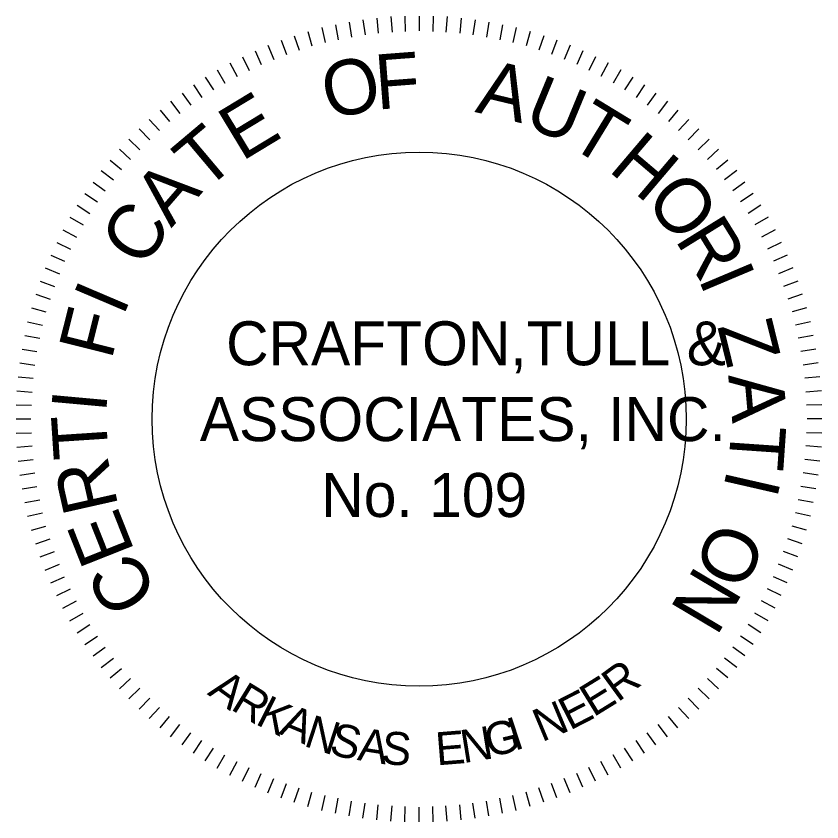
# Model space of a CAD drawing. Extents: x 670147 to 673275, y 705573 to 707613.
# Drawn here: x 672318.1 to 672589.3, y 705642.6 to 705913.8 of the extents above; entities that cross this region are included whole.
import ezdxf

# ---------------------------------------------------------------- set-up
doc = ezdxf.new("R2010")
doc.units = 0
doc.layers.add('R_Border Prem', color=7, linetype='Continuous')

msp = doc.modelspace()

# ---------------------------------------------------------------- linework, layer by layer
at = {"layer": 'R_Border Prem'}
for p, q in [((672444.26, 705913.59), (672444.63, 705908.41)), ((672448.89, 705913.77), (672449.07, 705908.59)), ((672453.7, 705913.77), (672453.7, 705908.78)), ((672458.51, 705913.77), (672458.32, 705908.59)), ((672463.13, 705913.59), (672462.76, 705908.41)), ((672425.58, 705910.81), (672426.5, 705905.82)), ((672430.2, 705911.74), (672430.94, 705906.74)), ((672434.83, 705912.48), (672435.57, 705907.48)), ((672439.45, 705913.03), (672440.01, 705908.04)), ((672467.94, 705913.03), (672467.39, 705908.04)), ((672472.57, 705912.48), (672471.83, 705907.48)), ((672477.19, 705911.74), (672476.45, 705906.74)), ((672481.82, 705910.81), (672480.89, 705905.82)), ((672416.33, 705908.59), (672417.62, 705903.78)), ((672420.95, 705909.89), (672422.06, 705904.89)), ((672486.44, 705909.89), (672485.33, 705904.89)), ((672491.07, 705908.59), (672489.77, 705903.78)), ((672407.26, 705905.63), (672409.11, 705900.82)), ((672411.7, 705907.11), (672413.37, 705902.3)), ((672495.69, 705907.11), (672494.03, 705902.3)), ((672500.13, 705905.63), (672498.28, 705900.82)), ((672402.82, 705903.97), (672404.86, 705899.16)), ((672504.57, 705903.97), (672502.54, 705899.16)), ((672394.31, 705900.08), (672396.53, 705895.46)), ((672398.57, 705902.12), (672400.6, 705897.49)), ((672508.83, 705902.12), (672506.79, 705897.49)), ((672513.08, 705900.08), (672510.86, 705895.46)), ((672390.06, 705898.05), (672392.46, 705893.42)), ((672517.34, 705898.05), (672514.93, 705893.42)), ((672385.8, 705895.64), (672388.39, 705891.2)), ((672521.59, 705895.64), (672519, 705891.2)), ((672381.73, 705893.24), (672384.51, 705888.98)), ((672525.66, 705893.24), (672522.89, 705888.98)), ((672377.85, 705890.65), (672380.62, 705886.39)), ((672529.55, 705890.65), (672526.77, 705886.39)), ((672373.96, 705887.87), (672376.92, 705883.8)), ((672533.43, 705887.87), (672530.47, 705883.8)), ((672370.08, 705885.1), (672373.22, 705881.03)), ((672537.32, 705885.1), (672534.17, 705881.03)), ((672366.56, 705882.14), (672369.71, 705878.25)), ((672540.83, 705882.14), (672537.69, 705878.25)), ((672362.86, 705878.99), (672366.38, 705875.29)), ((672544.53, 705878.99), (672541.02, 705875.29)), ((672359.53, 705875.85), (672363.05, 705872.15)), ((672547.86, 705875.85), (672544.35, 705872.15)), ((672356.02, 705872.33), (672359.72, 705868.82)), ((672551.38, 705872.33), (672547.68, 705868.82)), ((672352.87, 705869), (672356.57, 705865.49)), ((672554.52, 705869), (672550.82, 705865.49)), ((672349.73, 705865.3), (672353.61, 705862.16)), ((672557.67, 705865.3), (672553.78, 705862.16)), ((672346.77, 705861.79), (672350.84, 705858.64)), ((672560.63, 705861.79), (672556.56, 705858.64)), ((672343.99, 705857.9), (672348.06, 705854.94)), ((672563.4, 705857.9), (672559.33, 705854.94)), ((672341.22, 705854.02), (672345.47, 705851.24)), ((672566.18, 705854.02), (672561.92, 705851.24)), ((672338.63, 705850.13), (672342.88, 705847.36)), ((672568.77, 705850.13), (672564.51, 705847.36)), ((672336.22, 705846.06), (672340.66, 705843.47)), ((672571.17, 705846.06), (672566.73, 705843.47)), ((672333.82, 705841.81), (672338.44, 705839.4)), ((672573.58, 705841.81), (672568.95, 705839.4)), ((672331.78, 705837.55), (672336.41, 705835.33)), ((672575.61, 705837.55), (672570.99, 705835.33)), ((672329.75, 705833.3), (672334.37, 705831.26)), ((672577.65, 705833.3), (672573.02, 705831.26)), ((672327.9, 705829.04), (672332.71, 705827.01)), ((672579.5, 705829.04), (672574.69, 705827.01)), ((672326.23, 705824.6), (672331.04, 705822.75)), ((672581.16, 705824.6), (672576.35, 705822.75)), ((672324.75, 705820.16), (672329.56, 705818.5)), ((672582.64, 705820.16), (672577.83, 705818.5)), ((672323.27, 705815.54), (672328.08, 705814.24)), ((672584.12, 705815.54), (672579.31, 705814.24)), ((672321.98, 705810.91), (672326.97, 705809.8)), ((672585.42, 705810.91), (672580.42, 705809.8)), ((672321.05, 705806.29), (672326.05, 705805.36)), ((672586.34, 705806.29), (672581.35, 705805.36)), ((672320.13, 705801.66), (672325.12, 705800.92)), ((672587.27, 705801.66), (672582.27, 705800.92)), ((672319.39, 705797.04), (672324.38, 705796.3)), ((672588.01, 705797.04), (672583.01, 705796.3)), ((672318.83, 705792.41), (672323.83, 705791.86)), ((672588.56, 705792.41), (672583.57, 705791.86)), ((672318.28, 705787.6), (672323.46, 705787.23)), ((672589.12, 705787.6), (672583.94, 705787.23)), ((672318.09, 705782.98), (672323.27, 705782.79)), ((672589.3, 705782.98), (672584.12, 705782.79)), ((672318.09, 705778.17), (672323.09, 705778.17)), ((672589.3, 705778.17), (672584.31, 705778.17)), ((672318.09, 705773.36), (672323.27, 705773.54)), ((672589.3, 705773.36), (672584.12, 705773.54)), ((672318.28, 705768.73), (672323.46, 705769.1)), ((672589.12, 705768.73), (672583.94, 705769.1)), ((672318.83, 705763.92), (672323.83, 705764.48)), ((672588.56, 705763.92), (672583.57, 705764.48)), ((672319.39, 705759.3), (672324.38, 705760.04)), ((672588.01, 705759.3), (672583.01, 705760.04)), ((672320.13, 705754.67), (672325.12, 705755.41)), ((672587.27, 705754.67), (672582.27, 705755.41)), ((672321.05, 705750.05), (672326.05, 705750.97)), ((672586.34, 705750.05), (672581.35, 705750.97)), ((672321.98, 705745.42), (672326.97, 705746.53)), ((672585.42, 705745.42), (672580.42, 705746.53)), ((672323.27, 705740.8), (672328.08, 705742.09)), ((672584.12, 705740.8), (672579.31, 705742.09)), ((672324.75, 705736.17), (672329.56, 705737.84)), ((672582.64, 705736.17), (672577.83, 705737.84)), ((672326.23, 705731.73), (672331.04, 705733.58)), ((672581.16, 705731.73), (672576.35, 705733.58)), ((672327.9, 705727.29), (672332.71, 705729.33)), ((672579.5, 705727.29), (672574.69, 705729.33)), ((672329.75, 705723.04), (672334.37, 705725.07)), ((672577.65, 705723.04), (672573.02, 705725.07)), ((672331.78, 705718.78), (672336.41, 705721)), ((672575.61, 705718.78), (672570.99, 705721)), ((672333.82, 705714.53), (672338.44, 705716.93)), ((672573.58, 705714.53), (672568.95, 705716.93)), ((672336.22, 705710.27), (672340.66, 705712.86)), ((672571.17, 705710.27), (672566.73, 705712.86)), ((672338.63, 705706.2), (672342.88, 705708.98)), ((672568.77, 705706.2), (672564.51, 705708.98)), ((672341.22, 705702.32), (672345.47, 705705.09)), ((672566.18, 705702.32), (672561.92, 705705.09)), ((672343.99, 705698.43), (672348.06, 705701.39)), ((672563.4, 705698.43), (672559.33, 705701.39)), ((672346.77, 705694.55), (672350.84, 705697.69)), ((672560.63, 705694.55), (672556.56, 705697.69)), ((672349.73, 705691.03), (672353.61, 705694.18)), ((672557.67, 705691.03), (672553.78, 705694.18)), ((672352.87, 705687.33), (672356.57, 705690.85)), ((672554.52, 705687.33), (672550.82, 705690.85)), ((672356.02, 705684), (672359.72, 705687.52)), ((672551.38, 705684), (672547.68, 705687.52)), ((672359.53, 705680.49), (672363.05, 705684.19)), ((672547.86, 705680.49), (672544.35, 705684.19)), ((672362.86, 705677.34), (672366.38, 705681.04)), ((672544.53, 705677.34), (672541.02, 705681.04)), ((672366.56, 705674.2), (672369.71, 705678.08)), ((672540.83, 705674.2), (672537.69, 705678.08)), ((672370.08, 705671.24), (672373.22, 705675.31)), ((672537.32, 705671.24), (672534.17, 705675.31)), ((672373.96, 705668.46), (672376.92, 705672.53)), ((672533.43, 705668.46), (672530.47, 705672.53)), ((672377.85, 705665.69), (672380.62, 705669.94)), ((672529.55, 705665.69), (672526.77, 705669.94)), ((672381.73, 705663.1), (672384.51, 705667.35)), ((672525.66, 705663.1), (672522.89, 705667.35)), ((672385.8, 705660.69), (672388.39, 705665.13)), ((672521.59, 705660.69), (672519, 705665.13)), ((672390.06, 705658.29), (672392.46, 705662.91)), ((672517.34, 705658.29), (672514.93, 705662.91)), ((672394.31, 705656.25), (672396.53, 705660.88)), ((672398.57, 705654.22), (672400.6, 705658.84)), ((672508.83, 705654.22), (672506.79, 705658.84)), ((672513.08, 705656.25), (672510.86, 705660.88)), ((672402.82, 705652.37), (672404.86, 705657.18)), ((672504.57, 705652.37), (672502.54, 705657.18)), ((672407.26, 705650.7), (672409.11, 705655.51)), ((672411.7, 705649.22), (672413.37, 705654.03)), ((672495.69, 705649.22), (672494.03, 705654.03)), ((672500.13, 705650.7), (672498.28, 705655.51)), ((672416.33, 705647.74), (672417.62, 705652.55)), ((672420.95, 705646.45), (672422.06, 705651.44)), ((672425.58, 705645.52), (672426.5, 705650.52)), ((672481.82, 705645.52), (672480.89, 705650.52)), ((672486.44, 705646.45), (672485.33, 705651.44)), ((672491.07, 705647.74), (672489.77, 705652.55)), ((672430.2, 705644.6), (672430.94, 705649.59)), ((672434.83, 705643.86), (672435.57, 705648.85)), ((672439.45, 705643.3), (672440.01, 705648.3)), ((672444.26, 705642.75), (672444.63, 705647.93)), ((672448.89, 705642.56), (672449.07, 705647.74)), ((672458.51, 705642.56), (672458.32, 705647.74)), ((672463.13, 705642.75), (672462.76, 705647.93)), ((672467.94, 705643.3), (672467.39, 705648.3)), ((672472.57, 705643.86), (672471.83, 705648.85)), ((672477.19, 705644.6), (672476.45, 705649.59)), ((672453.7, 705642.56), (672453.7, 705647.56))]:
    msp.add_line(p, q, dxfattribs=at)
msp.add_circle((672453.78, 705778.12), 89.89, dxfattribs=at)

# ---------------------------------------------------------------- texts
for s, height, rotation, p in [('F', 18.5, 4.3732, (672439.53, 705882.28)), ('O', 18.5, 13.3113, (672423.44, 705878.76)), ('A', 18.5, 346.4969, (672472.28, 705881.54)), ('U', 18.5, 337.5588, (672488.19, 705877.28)), ('E', 18.5, 31.1876, (672394.02, 705864.7)), ('T', 18.5, 328.6206, (672503.17, 705870.62)), ('T', 18.5, 40.1257, (672381.44, 705854.53)), ('H', 18.5, 319.6825, (672517.05, 705861.93)), ('A', 18.5, 49.0639, (672370.34, 705842.32)), ('O', 18.5, 310.7444, (672529.26, 705851.2)), ('C', 18.5, 58.002, (672361.28, 705828.44)), ('R', 18.5, 301.8062, (672539.62, 705838.62)), ('I', 18.5, 292.8681, (672547.57, 705825.48)), ('I', 18.5, 66.9402, (672354.06, 705812.35)), ('F', 18.5, 75.8783, (672350.18, 705797.73)), ('Z', 18.5, 283.9299, (672554.05, 705809.39)), ('A', 18.5, 274.9918, (672557.75, 705792.92)), ('I', 18.5, 84.8164, (672348.33, 705779.97)), ('T', 18.5, 93.7546, (672349.25, 705765.17)), ('T', 18.5, 266.0537, (672558.86, 705776.64)), ('R', 18.5, 102.6927, (672352.58, 705748.71)), ('I', 18.5, 257.1155, (672557.56, 705761.66)), ('E', 18.5, 111.6308, (672358.13, 705733.54)), ('O', 18.5, 248.1774, (672553.31, 705744.64)), ('C', 18.5, 120.569, (672366.27, 705719.29)), ('N', 18.5, 239.2393, (672547.02, 705729.47)), ('R', 11.1, 36.1806, (672520.56, 705682.66)), ('A', 11.1, 324.001, (672382.18, 705685.62)), ('E', 11.1, 31.6694, (672512.42, 705677.67)), ('R', 11.1, 328.5123, (672389.95, 705680.63)), ('E', 11.1, 27.1582, (672504.47, 705673.23)), ('K', 11.1, 333.0235, (672398.28, 705675.63)), ('N', 11.1, 22.647, (672495.03, 705669.34)), ('A', 11.1, 337.5347, (672406.23, 705672.3)), ('N', 11.1, 342.0459, (672414.56, 705668.23)), ('I', 11.1, 18.1357, (672485.78, 705666.38)), ('S', 11.1, 346.5572, (672423.07, 705665.46)), ('G', 11.1, 13.6245, (672477.27, 705664.16)), ('A', 11.1, 351.0684, (672432.69, 705663.42)), ('S', 11.1, 355.5796, (672440.83, 705662.13)), ('E', 11.1, 4.6021, (672459.7, 705661.57)), ('N', 11.1, 9.1133, (672468.58, 705662.31))]:
    msp.add_text(s, height=height, rotation=rotation, dxfattribs=at).set_placement(p)
for s, height, p in [('CRAFTON,TULL &', 14.7996, (672388.78, 705796.25)), ('ASSOCIATES, INC.', 14.7996, (672379.92, 705770.72)), ('No. 109', 14.8, (672420.81, 705745.19))]:
    msp.add_text(s, height=height, dxfattribs=at).set_placement(p)

doc.saveas('drawing.dxf')
